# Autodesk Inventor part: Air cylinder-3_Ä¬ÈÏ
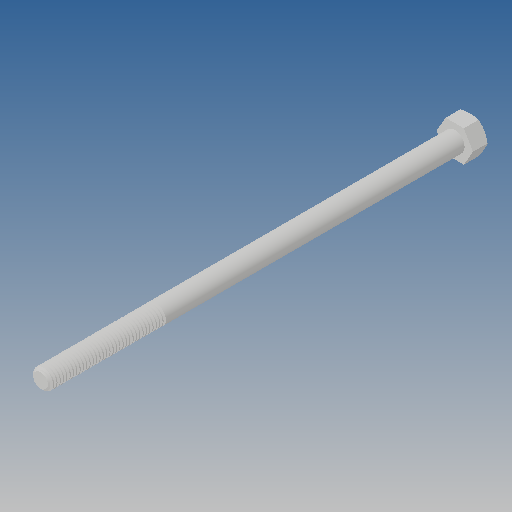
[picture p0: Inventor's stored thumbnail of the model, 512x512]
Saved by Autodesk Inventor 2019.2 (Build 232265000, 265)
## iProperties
Created: 2010-06
Part Number: Air cylinder-3_Ä¬ÈÏ
Material: Ogólny
Document SubType Name: Modeling
Designer: CADENGINEERING4
Density: 1 g/cm^3
Appearance: Domyślna
Author: CADENGINEERING4
Revision Number: ÈÎºÎ
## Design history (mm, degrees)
feature "NONE"
node "Bryła1"
